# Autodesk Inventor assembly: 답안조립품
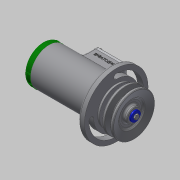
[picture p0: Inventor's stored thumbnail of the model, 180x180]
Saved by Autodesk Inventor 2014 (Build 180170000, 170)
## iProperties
Created: 2017-05
Part Number: 답안조립품
Document SubType Name: Assembly
Designer: Administrator
Author: Administrator
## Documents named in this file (19)
- C:\Users\Administrator\Desktop\470508V1003\답안조립품.iam
- C:\Users\Administrator\Desktop\470508V1003\1-본체.ipt
- C:\Users\Administrator\Desktop\470508V1003\축.ipt
- C:\Users\Administrator\Desktop\470508V1003\부시1.ipt
- C:\Users\Administrator\Desktop\470508V1003\베어링 15 x 35 x 11.ipt
- C:\Users\Administrator\Desktop\470508V1003\멈춤링 15 x 1.ipt
- C:\Users\Administrator\Desktop\470508V1003\멈춤링 35x1.6.ipt
- C:\Users\Administrator\Desktop\470508V1003\부시2.ipt
- C:\Users\Administrator\Desktop\470508V1003\와셔 10x21.ipt
- C:\Users\Administrator\Desktop\470508V1003\너트 M10.ipt
- C:\Users\Administrator\Desktop\470508V1003\키 4 x 4 x 18.ipt
- C:\Users\Administrator\Desktop\470508V1003\V-벨트풀리.ipt
- C:\Users\Administrator\Desktop\470508V1003\볼트 M4 x 10.ipt
- C:\Users\Administrator\Desktop\470508V1003\와셔 4x16.ipt
- C:\Users\Administrator\Desktop\470508V1003\탑 커버.ipt
- C:\Users\Administrator\Desktop\470508V1003\사이드 커버.ipt
- 사이드 커버.ipt
- C:\Users\Administrator\Desktop\470508V1003\십자볼트 M3 x 10.ipt
- C:\Users\Administrator\Desktop\470508V1003\와셔 3x6.ipt
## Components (3 placed, 3 different names)
1. 1-본체:1 — Mate:29, Mate:30, Mate:31, Mate:32, Mate:33, Mate:50, Flush:1
2. V-벨트풀리:1 — Mate:21, Angle:2, Mate:22, Mate:26
3. ISO 4017 M4 x 10:1 — Mate:27, Mate:28
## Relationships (13: Mate 11, Angle 1, Flush 1)
- Mate:21: V-벨트풀리:1
- Angle:2: V-벨트풀리:1
- Mate:22: V-벨트풀리:1
- Mate:26: V-벨트풀리:1
- Mate:27: ISO 4017 M4 x 10:1
- Mate:28: ISO 4017 M4 x 10:1
- Mate:29: 1-본체:1
- Mate:30: 1-본체:1
- Mate:31: 1-본체:1
- Mate:32: 1-본체:1
- Mate:33: 1-본체:1
- Mate:50: 1-본체:1
- Flush:1: 1-본체:1
